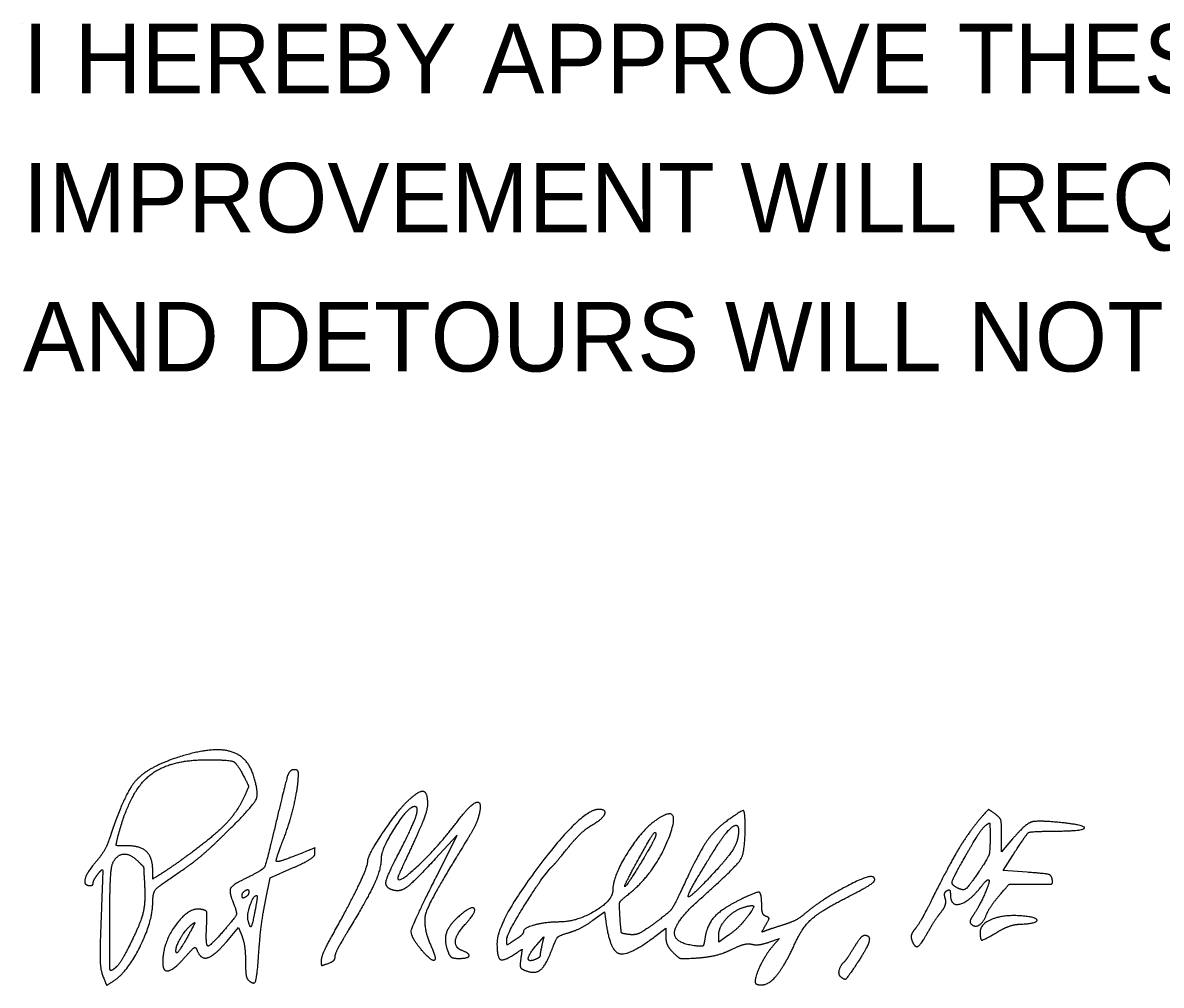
# Model space of a CAD drawing. Extents: x -8.3 to 42.1, y 0 to 22.
# Drawn here: x 24.528 to 26.821, y 8.939 to 10.877 of the extents above; entities that cross this region are included whole.
import ezdxf

# ---------------------------------------------------------------- set-up
doc = ezdxf.new("R2010")
doc.units = 0
doc.layers.add('SH_Data', color=7, linetype='Continuous')
doc.layers.add('SH_Text', color=7, linetype='Continuous')

msp = doc.modelspace()

# ---------------------------------------------------------------- linework, layer by layer
at = {"layer": 'SH_Data'}
msp.add_line((24.5279, 10.875), (24.5279, 10.875), dxfattribs=at)
at = {"layer": 'SH_Text'}
for p, q in [((25.1298, 8.9903), (25.1298, 8.9903)), ((25.3839, 9.0082), (25.3839, 9.0082)), ((26.1747, 8.9573), (26.1747, 8.9573))]:
    msp.add_line(p, q, dxfattribs=at)
for points in [[(25.3624, 9.1605), (25.4028, 9.2412), (25.3588, 9.1936)], [(26.522, 9.234), (26.4998, 9.2081), (26.4998, 9.2412)], [(26.5512, 9.1666), (26.5026, 9.17), (26.5218, 9.2)], [(25.0169, 9.1094), (25.0265, 9.1555), (25.0715, 9.1754)], [(25.6766, 9.0701), (25.6998, 9.0873), (25.7018, 9.072)], [(24.9391, 9.0276), (24.9628, 9.0552), (24.9696, 9.0372)], [(25.5637, 9.0209), (25.5775, 9.0366), (25.5738, 9.02)], [(25.8015, 9.0375), (25.8232, 9.054), (25.8232, 9.037)], [(25.9495, 9.0398), (25.9298, 9.0257), (25.9298, 9.0394)], [(26.0309, 9.026), (26.0523, 9.0335), (26.0391, 9.0184)]]:
    msp.add_lwpolyline(points, dxfattribs=at)
for points in [[(24.9918, 9.364), (24.9786, 9.4037), (24.9017, 9.419), (24.8329, 9.3955)], [(24.8329, 9.3955), (24.7758, 9.376), (24.7306, 9.3206), (24.7031, 9.2362)], [(24.7194, 9.2374), (24.7414, 9.3251), (24.8197, 9.3933), (24.8985, 9.3933)], [(24.8985, 9.3933), (24.9444, 9.3933), (24.9594, 9.3865), (24.9733, 9.3596)], [(24.9376, 9.2465), (24.9919, 9.3), (25.0042, 9.3267), (24.9918, 9.364)], [(24.9733, 9.3596), (24.9828, 9.3414), (24.9826, 9.3375), (24.972, 9.3148)], [(25.0748, 9.3733), (25.0657, 9.3733), (25.0578, 9.3508), (25.0395, 9.2733)], [(25.0524, 9.2313), (25.066, 9.266), (25.0832, 9.3409), (25.0832, 9.3655)], [(25.0832, 9.3655), (25.0832, 9.3698), (25.0794, 9.3733), (25.0748, 9.3733)], [(24.972, 9.3148), (24.9586, 9.2864), (24.9104, 9.2371), (24.8606, 9.2009)], [(25.3023, 9.3092), (25.3255, 9.3313), (25.3432, 9.3288), (25.3432, 9.3034)], [(25.2232, 9.1907), (25.2232, 9.201), (25.2832, 9.291), (25.3023, 9.3092)], [(25.3142, 9.2983), (25.3003, 9.294), (25.2498, 9.2125), (25.2498, 9.1944)], [(25.2876, 9.2095), (25.3147, 9.2618), (25.3268, 9.3021), (25.3142, 9.2983)], [(25.3432, 9.3034), (25.3432, 9.294), (25.3297, 9.2575), (25.3132, 9.2222)], [(25.4052, 9.2712), (25.4304, 9.3047), (25.4539, 9.3106), (25.4467, 9.2816)], [(25.6877, 9.2933), (25.6543, 9.2933), (25.4832, 9.0676), (25.4832, 9.0235)], [(25.6744, 9.2616), (25.6964, 9.2746), (25.7043, 9.2933), (25.6877, 9.2933)], [(25.9832, 9.2554), (25.9832, 9.2897), (25.976, 9.2919), (25.9433, 9.2678)], [(26.4865, 9.2842), (26.4742, 9.2933), (26.4717, 9.2924), (26.4546, 9.272)], [(25.0395, 9.2733), (25.0187, 9.1849), (25.0121, 9.1713), (24.9824, 9.157)], [(25.2832, 9.1557), (25.2832, 9.141), (25.3667, 9.2201), (25.4052, 9.2712)], [(25.4467, 9.2816), (25.4443, 9.2715), (25.4339, 9.2498), (25.4236, 9.2333)], [(25.8029, 9.2712), (25.7737, 9.2508), (25.7165, 9.1576), (25.7165, 9.1307)], [(25.7461, 9.1209), (25.8029, 9.1655), (25.8571, 9.3092), (25.8029, 9.2712)], [(25.9433, 9.2678), (25.9195, 9.2502), (25.8867, 9.2001), (25.8575, 9.1366)], [(26.4546, 9.272), (26.4319, 9.245), (26.3931, 9.18), (26.3599, 9.1133)], [(26.4664, 9.2599), (26.4752, 9.2672), (26.4765, 9.264), (26.4765, 9.2349)], [(26.4998, 9.2412), (26.4998, 9.2666), (26.4967, 9.2767), (26.4865, 9.2842)], [(26.6182, 9.2668), (26.5705, 9.2716), (26.5475, 9.2638), (26.522, 9.234)], [(26.6104, 9.2496), (26.6641, 9.25), (26.6693, 9.2615), (26.6182, 9.2668)], [(24.8532, 9.1737), (24.8715, 9.1861), (24.9095, 9.2188), (24.9376, 9.2465)], [(25.6261, 9.2159), (25.6405, 9.2338), (25.6622, 9.2544), (25.6744, 9.2616)], [(25.763, 9.1833), (25.7898, 9.2321), (25.8032, 9.2518), (25.8032, 9.2427)], [(25.8032, 9.2427), (25.8032, 9.2389), (25.7925, 9.218), (25.7794, 9.1962)], [(25.8904, 9.111), (25.9641, 9.1768), (25.9832, 9.2065), (25.9832, 9.2554)], [(25.926, 9.2192), (25.9448, 9.249), (25.9698, 9.2671), (25.9698, 9.251)], [(25.9698, 9.251), (25.9698, 9.233), (25.9531, 9.2018), (25.9295, 9.1759)], [(26.4261, 9.1979), (26.4427, 9.2274), (26.4608, 9.2552), (26.4664, 9.2599)], [(26.5218, 9.2), (26.5503, 9.2447), (26.5583, 9.2492), (26.6104, 9.2496)], [(24.7031, 9.2362), (24.6984, 9.2218), (24.686, 9.2001), (24.6755, 9.1881)], [(24.7386, 9.22), (24.7165, 9.22), (24.7153, 9.2211), (24.7194, 9.2374)], [(24.7898, 9.1689), (24.7898, 9.1958), (24.7656, 9.22), (24.7386, 9.22)], [(25.039, 9.1886), (25.0377, 9.1899), (25.0437, 9.2091), (25.0524, 9.2313)], [(25.3132, 9.2222), (25.2967, 9.1869), (25.2832, 9.1569), (25.2832, 9.1557)], [(25.4236, 9.2333), (25.3496, 9.1139), (25.3314, 9.0597), (25.3509, 9.0169)], [(26.4765, 9.2349), (26.4765, 9.2083), (26.4721, 9.1949), (26.4548, 9.1691)], [(24.7101, 9.1871), (24.7184, 9.2027), (24.7449, 9.204), (24.7594, 9.1895)], [(24.8606, 9.2009), (24.8418, 9.1873), (24.8182, 9.171), (24.8082, 9.1646)], [(25.0759, 9.1997), (25.0569, 9.1922), (25.0403, 9.1872), (25.039, 9.1886)], [(25.0715, 9.1754), (25.0962, 9.1863), (25.1165, 9.1993), (25.1165, 9.2043)], [(25.1165, 9.2043), (25.1165, 9.2158), (25.1167, 9.2158), (25.0759, 9.1997)], [(25.2715, 9.1314), (25.2573, 9.1365), (25.2622, 9.1606), (25.2876, 9.2095)], [(25.5959, 9.18), (25.598, 9.1818), (25.6116, 9.198), (25.6261, 9.2159)], [(25.9295, 9.1759), (25.869, 9.1096), (25.8676, 9.1267), (25.926, 9.2192)], [(26.4046, 9.1388), (26.3981, 9.143), (26.4033, 9.1572), (26.4261, 9.1979)], [(24.6755, 9.1881), (24.6569, 9.1666), (24.65, 9.14), (24.6632, 9.14)], [(24.7032, 9.0696), (24.7032, 9.1289), (24.7061, 9.1797), (24.7101, 9.1871)], [(24.7594, 9.1895), (24.7716, 9.1773), (24.7711, 9.1787), (24.7733, 9.14)], [(25.151, 9.0387), (25.1874, 9.1039), (25.2232, 9.1793), (25.2232, 9.1907)], [(25.2498, 9.1944), (25.2498, 9.1734), (25.2229, 9.1145), (25.1842, 9.0508)], [(25.3588, 9.1936), (25.3143, 9.1456), (25.2868, 9.126), (25.2715, 9.1314)], [(25.5032, 9.0329), (25.5032, 9.0437), (25.5814, 9.1679), (25.5959, 9.18)], [(25.7794, 9.1962), (25.7473, 9.1427), (25.7356, 9.1335), (25.763, 9.1833)], [(24.6698, 9.1453), (24.6698, 9.1483), (24.6743, 9.1566), (24.6798, 9.1637)], [(24.6798, 9.1637), (24.6886, 9.1753), (24.6893, 9.166), (24.6857, 9.0766)], [(24.7898, 9.1071), (24.7898, 9.126), (24.8031, 9.1401), (24.8532, 9.1737)], [(24.8082, 9.1646), (24.79, 9.1531), (24.7898, 9.1532), (24.7898, 9.1689)], [(24.9824, 9.157), (24.9516, 9.1421), (24.9426, 9.1289), (24.9502, 9.11)], [(25.3319, 9.0095), (25.3082, 9.037), (25.3134, 9.0629), (25.3624, 9.1605)], [(26.2422, 9.1565), (26.2349, 9.1638), (26.1353, 9.1105), (26.0998, 9.0803)], [(26.1865, 9.1153), (26.2281, 9.1364), (26.2477, 9.1509), (26.2422, 9.1565)], [(26.4548, 9.1691), (26.4329, 9.1364), (26.4202, 9.1288), (26.4046, 9.1388)], [(26.474, 9.1513), (26.477, 9.1483), (26.4536, 9.096), (26.4415, 9.0786)], [(26.4588, 9.138), (26.4657, 9.1468), (26.4725, 9.1528), (26.474, 9.1513)], [(26.6017, 9.1527), (26.6002, 9.1608), (26.5885, 9.1641), (26.5512, 9.1666)], [(26.5594, 9.1427), (26.5966, 9.1421), (26.6034, 9.1438), (26.6017, 9.1527)], [(24.6632, 9.14), (24.6668, 9.14), (24.6698, 9.1424), (24.6698, 9.1453)], [(24.7733, 9.14), (24.7753, 9.1043), (24.7641, 9.0613), (24.7411, 9.0157)], [(24.9698, 9.1192), (24.9698, 9.1228), (24.9728, 9.1277), (24.9765, 9.13)], [(24.9765, 9.13), (24.9802, 9.1322), (24.9832, 9.1311), (24.9832, 9.1274)], [(25.7165, 9.1307), (25.7165, 9.1099), (25.6436, 9.0666), (25.6085, 9.0666)], [(25.8575, 9.1366), (25.8403, 9.0995), (25.829, 9.0848), (25.8016, 9.0646)], [(26.3863, 9.1138), (26.3843, 9.1202), (26.3857, 9.1274), (26.3896, 9.1298)], [(26.3896, 9.1298), (26.3934, 9.1321), (26.3965, 9.1293), (26.3965, 9.1235)], [(26.3965, 9.1235), (26.3965, 9.0981), (26.4343, 9.1069), (26.4588, 9.138)], [(26.4952, 9.12), (26.5144, 9.1425), (26.5167, 9.1433), (26.5594, 9.1427)], [(24.7116, 8.9484), (24.7395, 8.9669), (24.7898, 9.069), (24.7898, 9.1071)], [(24.9502, 9.11), (24.9596, 9.0867), (24.957, 9.0771), (24.9348, 9.0515)], [(24.9765, 9.1166), (24.9728, 9.1144), (24.9698, 9.1155), (24.9698, 9.1192)], [(24.9832, 9.1274), (24.9832, 9.1237), (24.9802, 9.1189), (24.9765, 9.1166)], [(24.9816, 9.0711), (24.9792, 9.0817), (24.9929, 9.12), (24.9991, 9.12)], [(24.9991, 9.12), (25.0004, 9.12), (24.9992, 9.1078), (24.9964, 9.093)], [(25.0036, 9.0072), (25.0057, 9.038), (25.0117, 9.084), (25.0169, 9.1094)], [(25.7311, 9.0754), (25.7293, 9.1031), (25.7314, 9.1092), (25.7461, 9.1209)], [(25.8832, 9.0185), (25.8393, 9.0235), (25.8428, 9.0685), (25.8904, 9.111)], [(25.9686, 9.1091), (25.9343, 9.092), (25.9057, 9.0593), (25.9021, 9.0333)], [(26.0165, 9.1), (26.0165, 9.1255), (26.0056, 9.1276), (25.9686, 9.1091)], [(26.0842, 9.0247), (26.0984, 9.0561), (26.1367, 9.09), (26.1865, 9.1153)], [(26.3599, 9.1133), (26.3462, 9.0858), (26.3305, 9.0582), (26.3249, 9.0519)], [(26.3773, 9.0859), (26.3843, 9.0948), (26.3884, 9.1073), (26.3863, 9.1138)], [(26.4694, 9.0815), (26.4727, 9.0898), (26.4843, 9.1071), (26.4952, 9.12)], [(24.8875, 9.092), (24.8629, 9.097), (24.8098, 9.0245), (24.8098, 8.9858)], [(24.8982, 9.058), (24.8995, 9.084), (24.8977, 9.0899), (24.8875, 9.092)], [(24.9964, 9.093), (24.9907, 9.0617), (24.9855, 9.0539), (24.9816, 9.0711)], [(25.4203, 9.0632), (25.4427, 9.0874), (25.4319, 9.1003), (25.4073, 9.0787)], [(25.9298, 9.0394), (25.9298, 9.0562), (25.961, 9.0907), (25.9815, 9.0966)], [(25.9815, 9.0966), (26.0001, 9.1019), (26.0006, 9.0936), (25.9829, 9.0711)], [(26.0248, 9.0781), (26.0202, 9.0797), (26.0165, 9.0896), (26.0165, 9.1)], [(26.3519, 9.0469), (26.3589, 9.0594), (26.3703, 9.077), (26.3773, 9.0859)], [(24.6857, 9.0766), (24.683, 9.0092), (24.6842, 8.9704), (24.6892, 8.9576)], [(24.7137, 8.9737), (24.7042, 8.9658), (24.7032, 8.9751), (24.7032, 9.0696)], [(24.8365, 9.009), (24.8365, 9.0185), (24.8557, 9.051), (24.8667, 9.0601)], [(24.8667, 9.0601), (24.875, 9.067), (24.8741, 9.0628), (24.8632, 9.043)], [(25.4073, 9.0787), (25.3865, 9.0606), (25.3761, 9.0293), (25.3839, 9.0082)], [(25.4132, 9.009), (25.3977, 9.015), (25.4013, 9.0427), (25.4203, 9.0632)], [(25.6085, 9.0666), (25.5809, 9.0665), (25.5365, 9.0545), (25.5365, 9.0471)], [(25.6288, 9.0455), (25.6423, 9.0496), (25.6638, 9.0606), (25.6766, 9.0701)], [(25.7018, 9.072), (25.7098, 9.0098), (25.7479, 8.9967), (25.8015, 9.0375)], [(25.7502, 9.0413), (25.7349, 9.0431), (25.733, 9.0466), (25.7311, 9.0754)], [(25.8016, 9.0646), (25.7786, 9.0477), (25.7616, 9.04), (25.7502, 9.0413)], [(25.9829, 9.0711), (25.9754, 9.0616), (25.9604, 9.0475), (25.9495, 9.0398)], [(26.0243, 9.0488), (26.017, 9.0458), (26.017, 9.0477), (26.0243, 9.0601)], [(26.0243, 9.0601), (26.0313, 9.0719), (26.0314, 9.0757), (26.0248, 9.0781)], [(26.0598, 9.0607), (26.0452, 9.0561), (26.0292, 9.0508), (26.0243, 9.0488)], [(26.0998, 9.0803), (26.0925, 9.074), (26.0745, 9.0652), (26.0598, 9.0607)], [(26.4415, 9.0786), (26.4372, 9.0724), (26.4356, 9.0652), (26.4381, 9.0628)], [(26.4381, 9.0628), (26.4457, 9.0552), (26.4631, 9.0655), (26.4694, 9.0815)], [(26.5404, 9.0788), (26.5048, 9.0817), (26.4565, 9.0628), (26.4565, 9.0461)], [(26.493, 9.0474), (26.5062, 9.0552), (26.527, 9.062), (26.5392, 9.0624)], [(26.5392, 9.0624), (26.5707, 9.0637), (26.5716, 9.0762), (26.5404, 9.0788)], [(24.8632, 9.043), (24.8476, 9.0149), (24.8365, 9.0007), (24.8365, 9.009)], [(24.9348, 9.0515), (24.9053, 9.0174), (24.8962, 9.0191), (24.8982, 9.058)], [(24.9696, 9.0372), (24.9734, 9.0272), (24.9765, 9.0048), (24.9765, 8.9873)], [(25.1298, 8.9903), (25.1298, 8.996), (25.1394, 9.0178), (25.151, 9.0387)], [(25.1842, 9.0508), (25.169, 9.0258), (25.1565, 9.0014), (25.1565, 8.9967)], [(25.5365, 9.0471), (25.5365, 9.044), (25.529, 9.0366), (25.5198, 9.0306)], [(25.593, 9.0086), (25.6024, 9.0332), (25.6085, 9.0394), (25.6288, 9.0455)], [(25.8232, 9.037), (25.8232, 9.0276), (25.8295, 9.0136), (25.8372, 9.0059)], [(26.2024, 9.015), (26.2107, 9.0287), (26.2203, 9.04), (26.2237, 9.04)], [(26.2237, 9.04), (26.2359, 9.04), (26.2294, 9.0149), (26.2092, 8.9844)], [(26.3249, 9.0519), (26.3194, 9.0456), (26.3167, 9.0356), (26.319, 9.0297)], [(26.319, 9.0297), (26.325, 9.0142), (26.3372, 9.0207), (26.3519, 9.0469)], [(26.4565, 9.0461), (26.4565, 9.0297), (26.4635, 9.03), (26.493, 9.0474)], [(24.7411, 9.0157), (24.7318, 8.9974), (24.7195, 8.9785), (24.7137, 8.9737)], [(24.8552, 8.9962), (24.8701, 9.0132), (24.8763, 9.0166), (24.8791, 9.0096)], [(24.8791, 9.0096), (24.8864, 8.9905), (24.9146, 8.999), (24.9391, 9.0276)], [(25.3509, 9.0169), (25.3624, 8.9916), (25.3511, 8.9872), (25.3319, 9.0095)], [(25.4832, 9.0235), (25.4832, 8.9952), (25.4962, 8.9872), (25.5186, 9.0019)], [(25.5198, 9.0306), (25.504, 9.0202), (25.5032, 9.0203), (25.5032, 9.0329)], [(25.5598, 8.9909), (25.5452, 8.9853), (25.5474, 9.0024), (25.5637, 9.0209)], [(25.5738, 9.02), (25.5717, 9.0108), (25.57, 9.0014), (25.5699, 8.999)], [(25.9021, 9.0333), (25.9002, 9.0199), (25.8965, 9.017), (25.8832, 9.0185)], [(25.9555, 9.0113), (25.971, 9.0189), (25.9895, 9.0237), (25.9966, 9.0219)], [(25.9966, 9.0219), (26.0036, 9.02), (26.0191, 9.0219), (26.0309, 9.026)], [(26.0391, 9.0184), (26.0256, 9.0029), (26.0032, 8.958), (26.0032, 8.9464)], [(26.0165, 8.94), (26.0315, 8.94), (26.0646, 8.9814), (26.0842, 9.0247)], [(26.183, 8.9866), (26.1853, 8.9885), (26.194, 9.0012), (26.2024, 9.015)], [(24.8098, 8.9858), (24.8098, 8.9656), (24.8331, 8.971), (24.8552, 8.9962)], [(24.9811, 8.9509), (24.9933, 8.9387), (25.0002, 8.9559), (25.0036, 9.0072)], [(25.146, 8.984), (25.131, 8.9783), (25.1298, 8.9787), (25.1298, 8.9903)], [(25.1565, 8.9967), (25.1565, 8.9919), (25.1518, 8.9862), (25.146, 8.984)], [(25.3839, 9.0082), (25.3876, 8.9981), (25.3949, 8.9933), (25.4063, 8.9933)], [(25.4063, 8.9933), (25.4248, 8.9933), (25.429, 9.003), (25.4132, 9.009)], [(25.5186, 9.0019), (25.5336, 9.0117), (25.5339, 9.0114), (25.5312, 8.9927)], [(25.5312, 8.9927), (25.5292, 8.979), (25.5316, 8.9722), (25.5395, 8.9692)], [(25.5395, 8.9692), (25.5593, 8.9616), (25.5812, 8.9777), (25.593, 9.0086)], [(25.5699, 8.999), (25.5699, 8.9966), (25.5653, 8.993), (25.5598, 8.9909)], [(25.8372, 9.0059), (25.8491, 8.994), (25.8573, 8.9922), (25.8893, 8.9945)], [(25.8893, 8.9945), (25.9102, 8.9961), (25.94, 9.0036), (25.9555, 9.0113)], [(24.9765, 8.9873), (24.9765, 8.9698), (24.9786, 8.9535), (24.9811, 8.9509)], [(26.1747, 8.9573), (26.1705, 8.9615), (26.176, 8.981), (26.183, 8.9866)], [(26.2092, 8.9844), (26.1891, 8.954), (26.1829, 8.9491), (26.1747, 8.9573)], [(24.6892, 8.9576), (24.6963, 8.9396), (24.6976, 8.9391), (24.7116, 8.9484)], [(26.0032, 8.9464), (26.0032, 8.9429), (26.0091, 8.94), (26.0165, 8.94)]]:
    msp.add_open_spline(points, degree=2, dxfattribs=at)

# ---------------------------------------------------------------- texts
for s, p in [('I HEREBY APPROVE THESE PLANS AND DECLARE THAT THE MAKING OF THIS ', (24.5279, 10.735)), ('IMPROVEMENT WILL REQUIRE THE CLOSING TO TRAFFIC OF THE HIGHWAY ', (24.5279, 10.455)), ('AND DETOURS WILL NOT BE PROVIDED.', (24.5279, 10.175))]:
    msp.add_text(s, height=0.14, dxfattribs=at).set_placement(p)

doc.saveas('drawing.dxf')
